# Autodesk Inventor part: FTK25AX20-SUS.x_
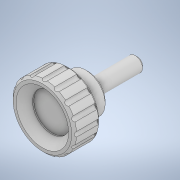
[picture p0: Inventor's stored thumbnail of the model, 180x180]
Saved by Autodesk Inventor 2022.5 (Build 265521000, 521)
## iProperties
Created: 2023-10
Part Number: FTK25AX20-SUS.x_
Material: 一般
Document SubType Name: Modeling
Designer: ImaoCorp
Density: 1 g/cm^3
Appearance: 既定
Sending System: SOLIDWORKS 2021-2021301
MC: AMD64
MC_MODEL: Intel64 Family 6 Model 60 Stepping 3, GenuineIntel
OS: Windows_NT
FRU: Parasolid Version 32.1, build 255,  1- 1-2021
FORMAT: text
GUISE: transmit
KEY: FTK25AX20-SUS
FILE: FTK25AX20-SUS.x_t
DATE: Tue Oct 17 11:07:39 2023
Author: ImaoCorp
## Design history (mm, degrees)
feature "Base1"
node "ソリッド1"
